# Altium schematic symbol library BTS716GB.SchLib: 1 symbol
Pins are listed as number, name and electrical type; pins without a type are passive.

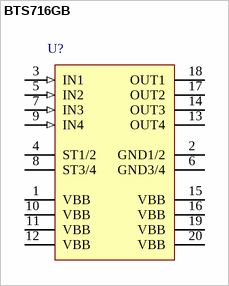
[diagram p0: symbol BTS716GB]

## BTS716GB
designator U?
Smart High-Side Power Switch, 4 Channels, 1.3 A Load Current, -40 to 150 degC, PG-DSO-20-31, Reel, Green; Manufacturer: Infineon; PartNumber: BTS716GB; Channels: 4; Green: TRUE; Group: Automotive Qualified; Load Current (typ): 1.3 A; Ptot (max): 3.6 W; Recommended Operating Voltage Max.: 40 V; Recommended Operating Voltage Min.: 5.5 V; RON @ 25degreesC: 140 mOhm; RON(max) @ 150degreesC: 280 mOhm; toff (max): 270 us; ton (max): 250 us
footprint INF-PG-DSO-20-31_N (SOP, 20-Leads, Body 12.7x7.5mm, Pitch 1.27mm, IPC High Density)
footprint INF-PG-DSO-20-31_L (SOP, 20-Leads, Body 12.7x7.5mm, Pitch 1.27mm, IPC High Density)
footprint INF-PG-DSO-20-31_M (SOP, 20-Leads, Body 12.7x7.5mm, Pitch 1.27mm, IPC Low Density)
pins: 1 VBB (power) "Positive power supply voltage. Design the wiring for the simultaneous max. short circuit currents from channel 1 to 2 and also for low thermal resistance", 2 GND1/2 (power) "Ground of chip 1 (channel 1,2)", 3 IN1 (in) "Input 1 activates channel 1 in case of logic high signal", 4 ST1/2 (oc) "Diagnostic feedback 1/2,3/4 of channel 1,2,3,4 open drain, low on failure", 5 IN2 (in) "Input 2 activates channel 2 in case of logic high signal", 6 GND3/4 (power) "Ground of chip 2 (channel 3,4)", 7 IN3 (in) "Input 3 activates channel 3 in case of logic high signal", 8 ST3/4 (oc) "Diagnostic feedback 1/2,3/4 of channel 1,2,3,4 open drain, low on failure", 9 IN4 (in) "Input 4 activates channel 4 in case of logic high signal", 10 VBB (power) "Positive power supply voltage. Design the wiring for the simultaneous max. short circuit currents from channel 1 to 2 and also for low thermal resistance", 11 VBB (power) "Positive power supply voltage. Design the wiring for the simultaneous max. short circuit currents from channel 1 to 2 and also for low thermal resistance", 12 VBB (power) "Positive power supply voltage. Design the wiring for the simultaneous max. short circuit currents from channel 1 to 2 and also for low thermal resistance", 13 OUT4 (power) "Output 1 protected high-side power output of channel 1. Design the wiring for the max. short circuit current", 14 OUT3 (power) "Output 1 protected high-side power output of channel 1. Design the wiring for the max. short circuit current", 15 VBB (power) "Positive power supply voltage. Design the wiring for the simultaneous max. short circuit currents from channel 1 to 2 and also for low thermal resistance", 16 VBB (power) "Positive power supply voltage. Design the wiring for the simultaneous max. short circuit currents from channel 1 to 2 and also for low thermal resistance", 17 OUT2 (power) "Output 1 protected high-side power output of channel 1. Design the wiring for the max. short circuit current", 18 OUT1 (power) "Output 1 protected high-side power output of channel 1. Design the wiring for the max. short circuit current", 19 VBB (power) "Positive power supply voltage. Design the wiring for the simultaneous max. short circuit currents from channel 1 to 2 and also for low thermal resistance", 20 VBB (power) "Positive power supply voltage. Design the wiring for the simultaneous max. short circuit currents from channel 1 to 2 and also for low thermal resistance"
